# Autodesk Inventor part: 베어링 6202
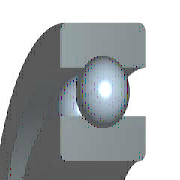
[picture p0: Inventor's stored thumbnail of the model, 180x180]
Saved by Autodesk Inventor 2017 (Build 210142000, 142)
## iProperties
IsCustomPart: 1
Created: 2015-12
Part Number: 베어링 6202
Material: 강철, 연강
Description: 깊은 그루브 볼 베어링
Document SubType Name: Modeling
Standard: KS B 2023
Designer: mdu
Standards Organization: KS
Language: ko-KR
Size Designation: 6202 - 15 x 35 x 11
Categories: <MemberInstance><Categories><Category DisplayName="샤프트 부품" InternalName="7f7aeb1f-a693-4053-b835-cee3144e0d98" Mnemonic="SHFT"><Category DisplayName="베어링" Inter
Density: 7.86 g/cm^3
Mass: 45.8724 g
Surface Area: 51.5584 cm^2
Volume: 5.83618 cm^3
Appearance: 노란색
Author: mdu
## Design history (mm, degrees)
sketch "스케치" dims "d0" = 5.2 (= -0.26 x WD + 0.26 x BD)
  geometry: L1 (2.9, 12.5)-(8.1, 12.5); L2 (5.5, 12.5)-(5.5, 9.9); L3 (5.5, 12.5)-(5.5, 15.1); L4 (3.568, 10.76)-(0, 10.76); L5 (0, 7.5)-(11, 7.5); L6 (3.568, 14.24)-(0, 14.24); L7 (0, 17.5)-(11, 17.5); L8 (11, 7.5)-(11, 10.76); L9 (7.432, 10.76)-(11, 10.76); L10 (7.432, 14.24)-(11, 14.24); L11 (11, 17.5)-(11, 14.24); L12 (-1.4, 0)-(8.4, 0) reference; L13 (0, -0.3)-(0, 5.3) reference
  constraints: 22 end point, 4 point on line, 2 collinear, 2 perpendicular, 2 symmetric about line, 1 midpoint, 1 parallel, 14 other
  dimensions: "d9" = 15 diameter of L5 L12 (= WD); "d11" = 35 diameter of L7 L12 (= BD); "d12" = 11 distance between parallel lines of L8 L13 (= KB); "d13" = 21.52 diameter of L9 L12 (= 0.326 x BD + 0.674 x WD)
revolve "본체" stored, may be unused: angle "d6" = 90 deg
revolve "볼" stored, may be unused: angle "d7" = 90 deg
pattern_circular "IDS_ARRAYBALL[SIMPL:T]" dims angle "d3" = 360 deg
body "Solid1"
fillet "모깎기1" dims "d1" = 0.6 (= KRS)
other parameters: "WD" = 15 [user parameter; used in 5 equation terms], "BD" = 35 [user parameter; used in 5 equation terms], "KB" = 11 [user parameter; used in 1 equation term], "KRS" = 0.6 [user parameter; used in 1 equation term], "d4" = 0, "d5" = 0, "d8" = 0, "d14" = 0, "d15" = 0, "BBA" = 0 [user parameter], "BC0" = 3750000 [user parameter], "BC" = 7800000 [user parameter], "BR" = 17.5 (= 0.5 x BD) [user parameter], "WR" = 7.5 (= 0.5 x WD) [user parameter]
